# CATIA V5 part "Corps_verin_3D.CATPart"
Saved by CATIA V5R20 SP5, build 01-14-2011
Part number: Corps_verin_3D
Bounding box of the stored display mesh (mm): x -54.975 to 54.975, y 18.983 to 368.933, z 73.206 to 183.202
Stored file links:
  J:\Thinkmotion\Projet IAO\A envoyer\Corps_verin_3D.CATPart
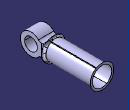
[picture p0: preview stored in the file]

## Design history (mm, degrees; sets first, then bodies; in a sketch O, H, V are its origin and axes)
Body1 (main body)
  Line1 to Line3: stored without definition
  Plane1: type Offset, RefPlane yz-plane, Offset -36
  Sketch1 on Plane1, origin (-36, 0, 0), H (0, 1, 0), V (0, 0, 1)
    circle A1 centre (68.933, 128.204) radius 30
    point P1 (68.933, 128.204)
    reference projected point E1 (68.933, 128.204) from Line1
    line L1 (112.2343, 153.204) -> (138.933, 153.204)
    line L2 (112.2343, 103.204) -> (138.933, 103.204)
    reference projected line E2 (68.933, 128.204) -> (233.933, 128.204) from Line2
    arc A2 centre (68.933, 128.204) radius 50 from (112.2343, 153.204) to (112.2343, 103.204) ccw
    line L3 (138.933, 153.204) -> (138.933, 103.204)
    reference projected point E3 (68.933, 128.204) from Line3
    radius A1 = 30
    distance L1 E2 = 25
    distance L1 L2 = 50
    radius A2 = 50
    distance L3 E3 = 70
    coincidence: E1 P1
    horizontal: L1 H, L2 H
    vertical: L3 V
  Pad1: profile Sketch1, direction (1, 0, 0), length 72
  Line4 to Line6: stored without definition
  Sketch2 on yz-plane, origin (0, 0, 0), H (0, 1, 0), V (0, 0, 1)
    line L1 (138.933, 128.204) -> (138.933, 183.204)
    line L2 (138.933, 183.204) -> (368.933, 183.204)
    line L3 (368.933, 183.204) -> (368.933, 173.204)
    line L4 (368.933, 173.204) -> (148.933, 173.204)
    line L5 (148.933, 173.204) -> (148.933, 128.204)
    line L6 (148.933, 128.204) -> (138.933, 128.204)
    reference projected line E1 (68.933, 128.204) -> (233.933, 128.204) from Line4
    reference projected line E2 (68.933, 128.204) -> (233.933, 128.204) from Line5
    reference intersected line E3 (138.933, 153.204) -> (138.933, 103.204) from face of Pad1 from Sketch1.L3
    distance L4 E2 = 45
    distance L4 L2 = 10
    distance L5 L1 = 10
    distance L5 L3 = 220
    vertical: L1 V, L3 V, L5 V
    horizontal: L2 H, L4 H, L6 H
    coincidence: L6 E1, L1 E3
  Shaft1: profile Sketch2, axis Line6, angle 360
  Fillet1: on edge [face of Shaft1 from Sketch2.L1 | end face of Pad1]; edge [face of Pad1 from Sketch1.L1 | end face of Pad1]; edge [face of Pad1 from Sketch1.L1 | face of Shaft1 from Sketch2.L1]; edge [face of Pad1 from Sketch1.A2 | face of Pad1 from Sketch1.L1]; edge [start face of Pad1 | face of Pad1 from Sketch1.L1]; edge [start face of Pad1 | face of Shaft1 from Sketch2.L1]; edge [start face of Pad1 | face of Pad1 from Sketch1.L2]; edge [face of Shaft1 from Sketch2.L1 | face of Pad1 from Sketch1.L2]; edge [face of Pad1 from Sketch1.L2 | face of Pad1 from Sketch1.A2]; edge [face of Pad1 from Sketch1.L2 | end face of Pad1]
  Fillet2: on edge [face of Fillet1 | face of Shaft1 from Sketch2.L2] (x2)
